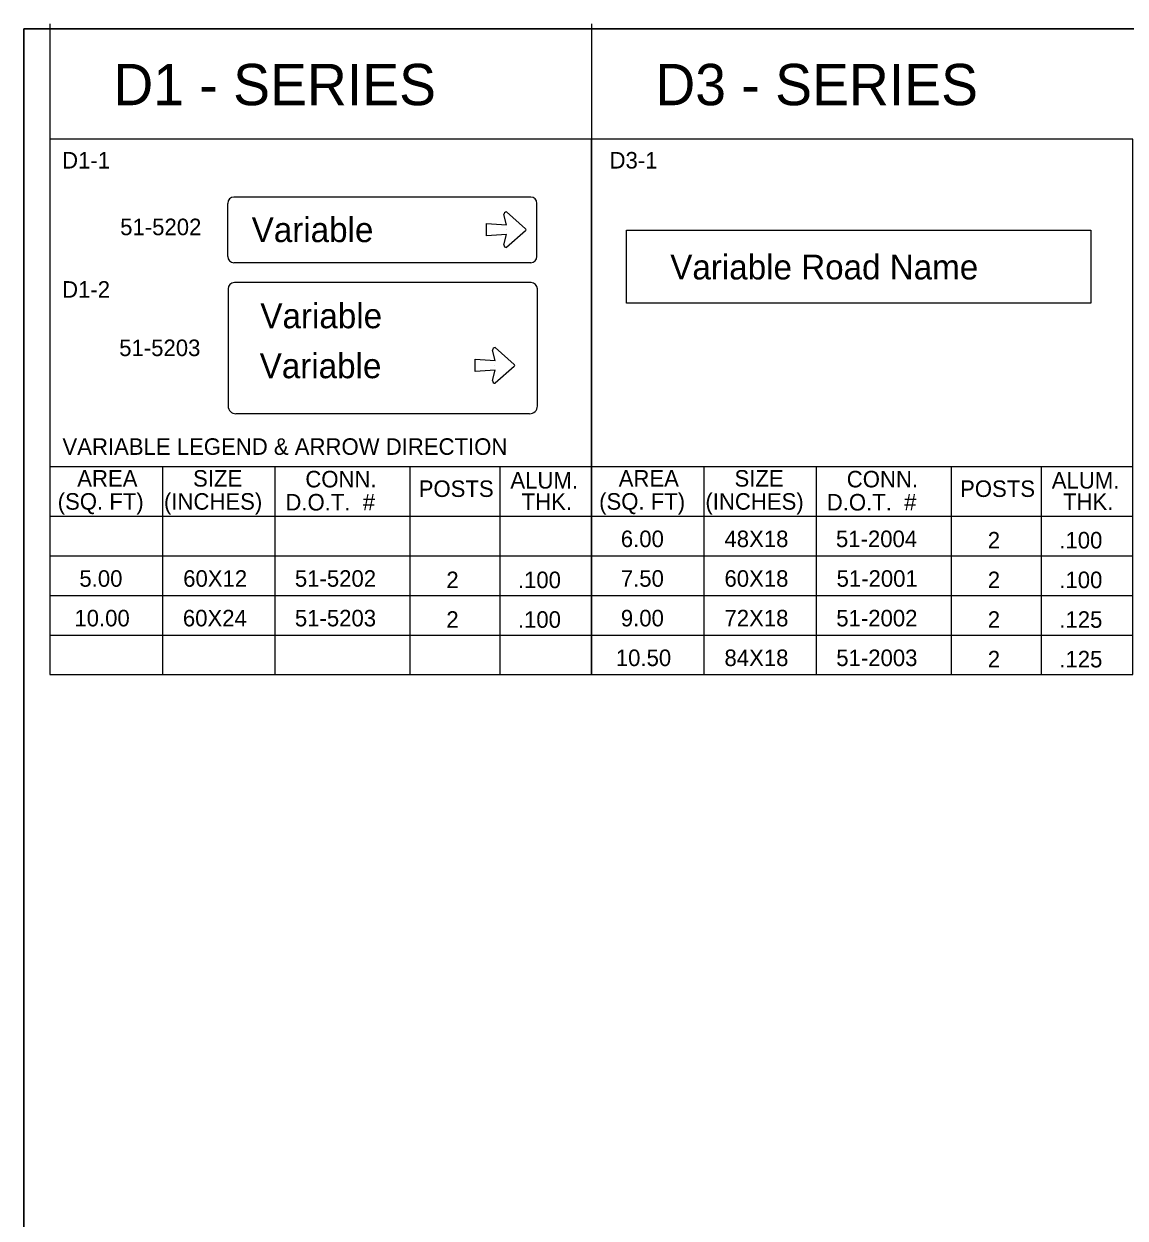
# Model space of a CAD drawing. Extents: x 0 to 2011, y -71 to 1183.
# Drawn here: x 0 to 213, y 598.9 to 830 of the extents above; entities that cross this region are included whole.
import ezdxf

# ---------------------------------------------------------------- set-up
doc = ezdxf.new("R2010")
doc.units = 0
for name, color, linetype in [('CT_Border_Perimeter_Shape', 7, 'Continuous'), ('CT_Construction', 7, 'Continuous'), ('Level 1', 7, 'Continuous'), ('Level 2', 7, 'Continuous'), ('Level 5', 7, 'Continuous')]:
    doc.layers.add(name, color=color, linetype=linetype)

msp = doc.modelspace()

# ---------------------------------------------------------------- linework, layer by layer
at = {"layer": 'CT_Border_Perimeter_Shape'}
msp.add_lwpolyline([(0, -0.97), (1270, -0.97), (1270, 829.03), (0, 829.03)], close=True, dxfattribs=at)
at = {"layer": 'CT_Construction'}
msp.add_lwpolyline([(0, 829.03), (1270, 829.03), (1270, 59.03), (0, 59.03)], close=True, dxfattribs=at)
at = {"layer": 'Level 1'}
for p, q in [((39.43, 784.99), (39.43, 795.27)), ((98.05, 796.48), (40.64, 796.48)), ((99.26, 784.99), (99.26, 795.27)), ((93.36, 791.11), (92.85, 793.1)), ((93.36, 793.61), (93.36, 793.61)), ((93.36, 793.61), (97.07, 790.36)), ((89.48, 788.97), (89.48, 791.37)), ((89.48, 791.37), (93.36, 791.11)), ((93.36, 789.22), (89.48, 788.97)), ((92.85, 787.23), (93.36, 789.22)), ((93.31, 790.17), (93.31, 790.17)), ((97.07, 789.98), (93.36, 786.72)), ((97.07, 789.98), (97.07, 789.98)), ((40.64, 783.79), (98.05, 783.79)), ((98.14, 779.93), (40.73, 779.93)), ((39.52, 778.72), (39.52, 756.05)), ((99.35, 756.05), (99.35, 778.72)), ((91.17, 767.35), (91.17, 767.35)), ((91.17, 767.35), (94.88, 764.09)), ((87.29, 762.7), (87.29, 765.1)), ((87.29, 765.1), (91.17, 764.85)), ((91.17, 764.85), (90.66, 766.84)), ((91.17, 762.96), (87.29, 762.7)), ((90.66, 760.97), (91.17, 762.96)), ((91.12, 763.9), (91.12, 763.9)), ((94.88, 763.71), (91.17, 760.46)), ((94.88, 763.71), (94.88, 763.71)), ((97.84, 754.54), (41.03, 754.54))]:
    msp.add_line(p, q, dxfattribs=at)
msp.add_lwpolyline([(116.6, 790.07), (206.41, 790.07), (206.41, 775.96), (116.6, 775.96)], close=True, dxfattribs=at)
for centre, radius, start, end in [((40.64, 795.27), 1.21, 90, 180), ((98.05, 795.27), 1.21, 360, 90), ((93.36, 793.1), 0.51, 90, 180), ((96.9, 790.17), 0.255, 311.213, 48.6399), ((93.36, 787.23), 0.51, 180, 270), ((40.64, 784.99), 1.21, 180, 270), ((98.05, 784.99), 1.21, 270, 0), ((40.73, 778.72), 1.21, 90, 180), ((98.14, 778.72), 1.21, 360, 90), ((91.17, 766.84), 0.51, 90, 180), ((94.71, 763.9), 0.255, 311.213, 48.6399), ((91.17, 760.97), 0.51, 180, 270), ((41.03, 756.05), 1.51, 180, 270), ((97.84, 756.05), 1.51, 270, 360)]:
    msp.add_arc(centre, radius, start, end, dxfattribs=at)
at = {"layer": 'Level 2'}
for p, q in [((5.05, 744.34), (109.8, 744.34)), ((26.8, 744.34), (26.8, 704.06)), ((48.55, 744.34), (48.55, 704.06)), ((74.65, 744.34), (74.65, 704.06)), ((92.05, 744.34), (92.05, 704.06)), ((109.8, 744.34), (214.55, 744.34)), ((131.55, 744.34), (131.55, 704.06)), ((153.3, 744.34), (153.3, 704.06)), ((179.4, 744.34), (179.4, 704.06)), ((196.8, 744.34), (196.8, 704.06)), ((5.05, 734.75), (109.8, 734.75)), ((109.8, 734.75), (214.55, 734.75)), ((5.05, 727.07), (109.8, 727.07)), ((109.8, 727.07), (214.55, 727.07)), ((5.05, 719.4), (109.8, 719.4)), ((109.8, 719.4), (214.55, 719.4)), ((5.05, 711.73), (109.8, 711.73)), ((109.8, 711.73), (214.55, 711.73))]:
    msp.add_line(p, q, dxfattribs=at)
for points in [[(109.8, 807.68), (5.05, 807.68), (5.05, 704.06), (109.8, 704.06)], [(214.55, 807.68), (109.8, 807.68), (109.8, 704.06), (214.55, 704.06)]]:
    msp.add_lwpolyline(points, close=True, dxfattribs=at)
at = {"layer": 'Level 5'}
for p, q in [((5.05, 830), (5.05, 704.06)), ((109.8, 830), (109.8, 704.54))]:
    msp.add_line(p, q, dxfattribs=at)
msp.add_lwpolyline([(5.05, 830), (5.05, 807.68)], dxfattribs=at)

# ---------------------------------------------------------------- texts
at = {"layer": 'Level 1'}
for s, height, p in [('D1 - SERIES', 8, (17.3, 814.26)), ('D3 - SERIES', 8, (122.16, 814.26)), ('Variable Road Name', 4.8, (125.05, 780.54))]:
    msp.add_text(s, height=height, dxfattribs=at).set_placement(p)
at = {"layer": 'Level 2'}
for s, height, p in [('D1-1', 3.2, (7.39, 802.01)), ('D3-1', 3.2, (113.31, 802.01)), ('Variable', 4.8, (44.07, 787.77)), ('51-5202', 3.2, (18.63, 789.11)), ('D1-2', 3.2, (7.39, 777.01)), ('Variable', 4.8, (45.75, 771.1)), ('51-5203', 3.2, (18.44, 765.71)), ('Variable', 4.8, (45.62, 761.43)), ('VARIABLE LEGEND & ARROW DIRECTION', 3.2, (7.46, 746.6)), ('AREA', 3.2, (10.32, 740.45)), ('SIZE', 3.2, (32.73, 740.45)), ('CONN.', 3.2, (54.45, 740.3)), ('ALUM.', 3.2, (94.12, 740.07)), ('AREA', 3.2, (115.07, 740.45)), ('SIZE', 3.2, (137.48, 740.45)), ('CONN.', 3.2, (159.2, 740.3)), ('ALUM.', 3.2, (198.86, 740.07)), ('POSTS', 3.2, (76.38, 738.45)), ('POSTS', 3.2, (181.12, 738.45)), ('(SQ. FT)', 3.2, (6.54, 735.98)), ('(INCHES)', 3.2, (27.1, 735.98)), ('D.O.T.  #', 3.2, (50.59, 735.83)), ('THK.', 3.2, (96.29, 735.93)), ('(SQ. FT)', 3.2, (111.29, 735.98)), ('(INCHES)', 3.2, (131.85, 735.98)), ('D.O.T.  #', 3.2, (155.33, 735.83)), ('THK.', 3.2, (201.04, 735.93))]:
    msp.add_text(s, height=height, dxfattribs=at).set_placement(p)
at = {"layer": 'Level 5'}
for s, p in [(' 6.00', (114.3, 728.74)), ('48X18', (135.54, 728.74)), ('51-2004', (157.11, 728.74)), ('2', (186.48, 728.48)), ('.100', (200.32, 728.48)), (' 5.00', (9.55, 721.07)), ('60X12', (30.82, 721.07)), ('51-5202', (52.43, 721.07)), ('2', (81.73, 720.8)), ('.100', (95.57, 720.8)), (' 7.50', (114.3, 721.07)), ('60X18', (135.54, 721.07)), ('51-2001', (157.23, 721.07)), ('2', (186.48, 720.8)), ('.100', (200.32, 720.8)), ('10.00', (9.77, 713.4)), ('60X24', (30.76, 713.4)), ('51-5203', (52.43, 713.4)), (' 9.00', (114.3, 713.4)), ('72X18', (135.54, 713.4)), ('51-2002', (157.17, 713.4)), ('2', (81.73, 713.13)), ('.100', (95.57, 713.13)), ('2', (186.48, 713.13)), ('.125', (200.32, 713.13)), ('10.50', (114.52, 705.72)), ('84X18', (135.54, 705.72)), ('51-2003', (157.17, 705.72)), ('2', (186.48, 705.46)), ('.125', (200.32, 705.46))]:
    msp.add_text(s, height=3.2, dxfattribs=at).set_placement(p)

doc.saveas('drawing.dxf')
